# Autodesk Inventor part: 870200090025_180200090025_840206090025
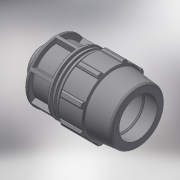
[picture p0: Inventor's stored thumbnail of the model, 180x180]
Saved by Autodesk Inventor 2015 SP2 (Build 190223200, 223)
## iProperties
Created: 2017-02
Part Number: 870200090025_180200090025_840206090025
Material: Generic
Description: PLASSON MALE ADAPTOR 90-2.1/2"
Document SubType Name: Modeling
Designer: KIM
Mass: 964.158 g
Surface Area: 1468.9 cm^2
Volume: 964.158 cm^3
Density: 1 g/cm^3
Appearance: Default
Author: KIM
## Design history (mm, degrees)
derived "87020.ipt"
feature "Solid1::87020.ipt"
tag "TaggingFeature1"
body "Solid1"
other parameters: "d4" = 32.71429, "d5" = 57.25, "d7" = 152, "d8" = 114, "d9" = 32.71429, "d11" = 6.54286, "d12" = 121.6, "d13" = 120 deg, "d14" = 117, "d15" = 6 deg, "d16" = 136.8, "d18" = 4.5, "d19" = 35 deg, "d20" = 17.5 deg, "d21" = 141.36, "d23" = 0, "d25" = 360 deg, "d27" = 3.04, "d34" = 7.6, "d36" = 0, "d42" = 57.25, "d43" = 4.56, "d46" = 2.7, "d49" = 169, "d51" = 229, "d52" = 29, "d53" = 1.8, "d55" = 360 deg, "d57" = 75.184, "d58" = 52.6288, "d59" = 45.8, "d61" = 134.064, "d62" = 5.32286, "d63" = 5.32286, "d66" = 10.64571, "E_" = 152, "H_" = 229, "l_" = 169, "l_2" = 29, "R_" = 75.184, "d60" = 26.61429
